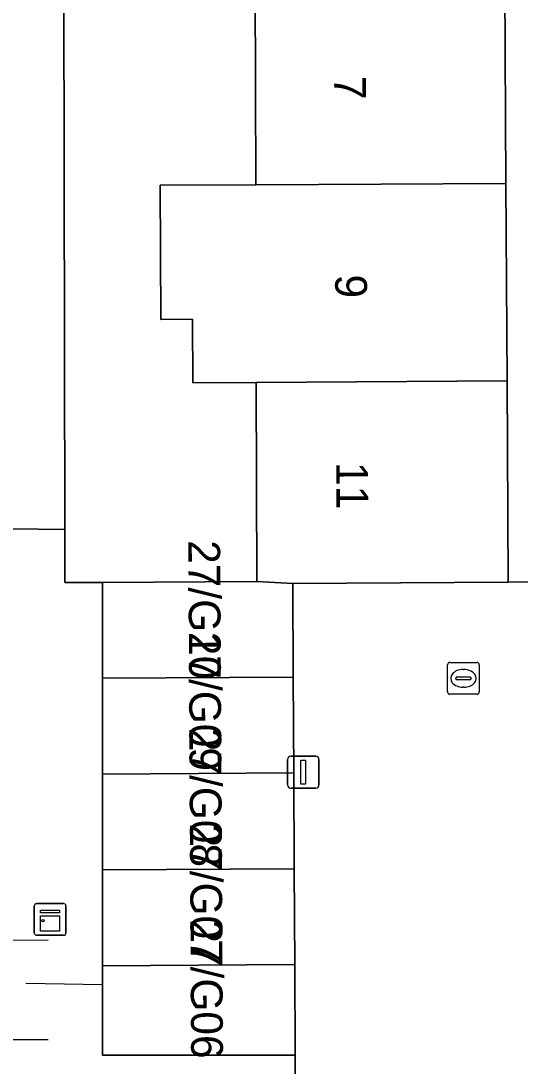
# Model space of a CAD drawing. Extents: x 160732 to 162107, y 387428 to 388479.
# Drawn here: x 161246.75 to 161262.48, y 387935.67 to 387968.6 of the extents above; entities that cross this region are included whole.
import ezdxf

# ---------------------------------------------------------------- set-up
doc = ezdxf.new("R2010")
doc.units = 0
for name, color, linetype in [('IMGEO_Erf', 7, 'Continuous'), ('IMGEO_Hek', 7, 'Continuous'), ('IMGEO_Kast', 7, 'Continuous'), ('IMGEO_Kolk', 7, 'Continuous'), ('IMGEO_Lichtmast', 7, 'Continuous'), ('IMGEO_Pand', 7, 'Continuous'), ('IMGEO_Pand_nummerreeks', 7, 'Continuous'), ('IMGEO_Rijbaan_lokaal_open', 7, 'Continuous'), ('IMGEO_Voetpad_open', 7, 'Continuous')]:
    doc.layers.add(name, color=color, linetype=linetype)

msp = doc.modelspace()

# ---------------------------------------------------------------- linework, layer by layer
at = {"layer": 'IMGEO_Erf'}
for points in [[(161269.286, 387988.563), (161261.937, 387988.543), (161261.937, 387985.351), (161261.931, 387982.158), (161261.966, 387975.932), (161262.001, 387969.706), (161262.035, 387963.48), (161262.07, 387957.254), (161262.106, 387950.91), (161265.944, 387950.957)], [(161248.071, 387986.562), (161248.135, 387952.571), (161248.138, 387950.901), (161249.328, 387950.908), (161254.189, 387950.935), (161254.17, 387957.21), (161252.17, 387957.199), (161252.159, 387959.199), (161251.159, 387959.193), (161251.135, 387963.419), (161254.152, 387963.436), (161254.133, 387969.662), (161254.114, 387975.888)]]:
    msp.add_lwpolyline(points, dxfattribs=at)
at = {"layer": 'IMGEO_Hek'}
for points in [[(161247.615, 387939.625), (161245.221, 387939.638)], [(161246.908, 387938.278), (161249.32, 387938.233)], [(161245.226, 387936.499), (161247.615, 387936.5)]]:
    msp.add_lwpolyline(points, dxfattribs=at)
at = {"layer": 'IMGEO_Kast'}
for p, q in [((161247.248, 387940.788), (161248.089, 387940.788)), ((161248.089, 387940.788), (161247.248, 387940.788)), ((161247.173, 387939.863), (161247.173, 387940.704)), ((161247.173, 387940.704), (161247.173, 387939.863)), ((161248.173, 387940.713), (161248.173, 387939.872)), ((161248.173, 387939.872), (161248.173, 387940.713)), ((161248.098, 387939.788), (161247.257, 387939.788)), ((161247.257, 387939.788), (161248.098, 387939.788))]:
    msp.add_line(p, q, dxfattribs=at)
for points in [[(161247.368, 387940.578), (161247.968, 387940.578), (161247.968, 387940.493), (161247.368, 387940.493), (161247.368, 387940.578)], [(161247.368, 387940.403), (161247.968, 387940.403), (161247.968, 387939.914), (161247.368, 387939.914), (161247.368, 387940.403)]]:
    msp.add_lwpolyline(points, dxfattribs=at)
msp.add_circle((161247.452, 387940.252), 0.0377, dxfattribs=at)
for centre, start, end in [((161247.251, 387940.71), 92.4484, 184.2845), ((161247.251, 387940.71), 92.4484, 184.2845), ((161248.095, 387940.71), 2.4484, 94.2845), ((161248.095, 387940.71), 2.4484, 94.2845), ((161247.251, 387939.866), 182.4484, 274.2845), ((161247.251, 387939.866), 182.4484, 274.2845), ((161248.095, 387939.866), 272.4484, 4.2845), ((161248.095, 387939.866), 272.4484, 4.2845)]:
    msp.add_arc(centre, 0.0779, start, end, dxfattribs=at)
at = {"layer": 'IMGEO_Kolk'}
for p, q in [((161260.194, 387947.458), (161260.194, 387948.31)), ((161260.269, 387948.384), (161261.121, 387948.384)), ((161261.195, 387948.31), (161261.195, 387947.458)), ((161260.682, 387948.164), (161260.707, 387948.164)), ((161260.453, 387947.878), (161260.453, 387947.89)), ((161260.891, 387947.841), (161260.493, 387947.841)), ((161260.496, 387947.927), (161260.894, 387947.927)), ((161260.937, 387947.89), (161260.937, 387947.878)), ((161261.121, 387947.384), (161260.269, 387947.384)), ((161260.705, 387947.604), (161260.68, 387947.604))]:
    msp.add_line(p, q, dxfattribs=at)
for points in [[(161260.194, 387947.458), (161260.194, 387948.31)], [(161260.269, 387948.384), (161261.121, 387948.384)], [(161261.195, 387948.31), (161261.195, 387947.458)], [(161261.121, 387947.384), (161260.269, 387947.384)]]:
    msp.add_lwpolyline(points, dxfattribs=at)
for centre, radius, start, end in [((161260.271, 387948.308), 0.0765, 91.552, 178.448), ((161260.271, 387948.308), 0.0765, 91.552, 178.448), ((161261.119, 387948.308), 0.0765, 1.552, 88.448), ((161261.119, 387948.308), 0.0765, 1.552, 88.448), ((161260.493, 387947.887), 0.0403, 85.8775, 175.7526), ((161260.49, 387947.877), 0.0366, 178.938, 274.7102), ((161260.894, 387947.884), 0.043, 264.8664, 352.4533), ((161260.898, 387947.889), 0.0386, 1.7309, 96.639), ((161260.271, 387947.46), 0.0765, 181.552, 268.448), ((161260.271, 387947.46), 0.0765, 181.552, 268.448), ((161261.119, 387947.46), 0.0765, 271.552, 358.448), ((161261.119, 387947.46), 0.0765, 271.552, 358.448)]:
    msp.add_arc(centre, radius, start, end, dxfattribs=at)
for centre, major_axis, ratio, start_param, end_param in [((161260.681, 387947.884), (-0.387, 0.002), 0.722429, 4.712389, 7.853982), ((161260.706, 387947.884), (-0.39, 0.002), 0.717154, 1.570796, 4.712389)]:
    msp.add_ellipse(centre, major_axis=major_axis, ratio=ratio, start_param=start_param, end_param=end_param, dxfattribs=at)
at = {"layer": 'IMGEO_Lichtmast'}
for p, q in [((161255.254, 387945.427), (161256.044, 387945.427)), ((161256.044, 387945.427), (161255.254, 387945.427)), ((161255.154, 387944.527), (161255.154, 387945.327)), ((161255.154, 387945.327), (161255.154, 387944.527)), ((161256.144, 387945.327), (161256.144, 387944.527)), ((161256.144, 387944.527), (161256.144, 387945.327)), ((161256.044, 387944.427), (161255.254, 387944.427)), ((161255.254, 387944.427), (161256.044, 387944.427))]:
    msp.add_line(p, q, dxfattribs=at)
msp.add_lwpolyline([(161255.574, 387945.302), (161255.724, 387945.302), (161255.724, 387944.552), (161255.574, 387944.552), (161255.574, 387945.302)], dxfattribs=at)
for centre, start, end in [((161255.254, 387945.327), 90, 180), ((161255.254, 387945.327), 90, 180), ((161256.044, 387945.327), 0, 90), ((161256.044, 387945.327), 360, 90), ((161255.254, 387944.527), 180, 270), ((161255.254, 387944.527), 180, 270), ((161256.044, 387944.527), 270, 0), ((161256.044, 387944.527), 270, 0)]:
    msp.add_arc(centre, 0.1, start, end, dxfattribs=at)
at = {"layer": 'IMGEO_Pand'}
for points in [[(161254.152, 387963.436), (161262.035, 387963.48), (161262.001, 387969.706), (161254.133, 387969.662)], [(161262.035, 387963.48), (161254.152, 387963.436), (161251.135, 387963.419), (161251.159, 387959.193), (161252.159, 387959.199), (161252.17, 387957.199), (161254.17, 387957.21), (161262.07, 387957.254)], [(161254.189, 387950.935), (161255.315, 387950.872), (161262.106, 387950.91), (161262.07, 387957.254), (161254.17, 387957.21)], [(161249.326, 387947.888), (161255.331, 387947.922), (161255.315, 387950.872), (161254.189, 387950.935), (161249.328, 387950.908)], [(161249.324, 387944.869), (161255.348, 387944.903), (161255.331, 387947.922), (161249.326, 387947.888)], [(161249.322, 387941.849), (161255.365, 387941.884), (161255.348, 387944.903), (161249.324, 387944.869)], [(161249.32, 387938.83), (161255.382, 387938.864), (161255.365, 387941.884), (161249.322, 387941.849)], [(161249.32, 387938.233), (161249.318, 387936.014), (161255.398, 387936.01), (161255.382, 387938.864), (161249.32, 387938.83)]]:
    msp.add_lwpolyline(points, close=True, dxfattribs=at)
at = {"layer": 'IMGEO_Rijbaan_lokaal_open'}
msp.add_lwpolyline([(161270.5, 387938.249), (161270.502, 387938.832), (161269.811, 387938.828), (161266.012, 387938.807), (161265.995, 387941.844), (161265.978, 387944.882), (161265.961, 387947.919), (161265.944, 387950.957), (161262.106, 387950.91), (161255.315, 387950.872), (161255.331, 387947.922), (161255.348, 387944.903), (161255.365, 387941.884), (161255.382, 387938.864), (161255.398, 387936.01), (161255.406, 387932.376)], dxfattribs=at)
at = {"layer": 'IMGEO_Voetpad_open'}
for points in [[(161220.883, 388007.94), (161217.385, 388007.635), (161217.501, 387972.088), (161217.515, 387971.998), (161217.376, 387967.03), (161217.48, 387956.261), (161217.496, 387954.255), (161217.507, 387952.589), (161243.083, 387952.638), (161248.135, 387952.571), (161248.071, 387986.562), (161248.067, 387986.627), (161248.197, 387991.584)], [(161249.47, 387932.343), (161255.406, 387932.376), (161255.398, 387936.01), (161249.318, 387936.014), (161249.32, 387938.233), (161249.32, 387938.83), (161249.322, 387941.849), (161249.324, 387944.869), (161249.326, 387947.888), (161249.328, 387950.908), (161248.138, 387950.901), (161248.135, 387952.571), (161243.083, 387952.638)]]:
    msp.add_lwpolyline(points, dxfattribs=at)

# ---------------------------------------------------------------- texts
at = {"layer": 'IMGEO_Pand_nummerreeks'}
for s, rotation, p in [('7', 270.3191, (161256.621, 387966.859)), ('9', 270.3206, (161256.655, 387960.606)), ('11', 270.3191, (161256.688, 387954.697)), ('27/G10', 270.3203, (161252.027, 387952.235)), ('27/G09', 270.3203, (161252.043, 387949.348)), ('27/G08', 270.3203, (161252.06, 387946.322)), ('27/G07', 270.3203, (161252.077, 387943.306)), ('27/G06', 270.3203, (161252.094, 387940.287))]:
    msp.add_text(s, height=1, rotation=rotation, dxfattribs=at).set_placement(p)

doc.saveas('drawing.dxf')
